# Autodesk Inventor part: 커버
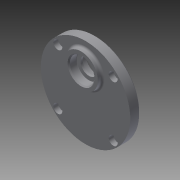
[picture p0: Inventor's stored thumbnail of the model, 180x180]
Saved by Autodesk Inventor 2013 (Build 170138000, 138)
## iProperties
Created: 2015-07
Part Number: 커버
Material: 일반
Document SubType Name: Modeling
Designer: user
Density: 1 g/cm^3
Author: user
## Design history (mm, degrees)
sketch "스케치1"
  geometry: C1 r 40 at (0, 0); 1 further point
  constraints: 1 centre point, 1 coincident
  dimensions: "d0" = 80 diameter of C1
extrude "돌출1" new body sketch "스케치1" distance "d1" = 9; taper "d2" = 0 deg
sketch "스케치2"
  geometry: L1 (0, 0)-(0, 11); L2 (0, 0)-(0, -20); C1 r 40 at (0, 0) reference; C2 r 14 at (0, 11); C3 r 14 at (0, -20)
  constraints: 4 end point, 2 centre point, 2 coincident, 1 collinear, 1 vertical
  dimensions: "d3" = 11 distance of L1.start L1.end; "d4" = 20 distance of L1.start L2.end; "d5" = 28 diameter of C2; "d6" = 28 diameter of C3
extrude "돌출2" join sketch "스케치2" distance "d7" = 3; taper "d8" = 0 deg
sketch "스케치3"
  geometry: C1 r 14 at (0, 0) reference; C2 r 14 at (0, -31) reference; C3 r 11 at (0, 0); C4 r 11 at (0, -29.914); 1 further point
  constraints: 2 centre point, 1 coincident
  dimensions: "d9" = 22 diameter of C3; "d10" = 22 diameter of C4
extrude "돌출3" cut sketch "스케치3" distance "d11" = 7; taper "d12" = 0 deg
sketch "스케치4"
  geometry: C1 r 9 at (0, 0); 2 further points
  constraints: 1 centre point, 1 coincident, 1 vertical alignment
  dimensions: "d13" = 18 diameter of C1
extrude "돌출4" cut sketch "스케치4" distance "d14" = 1; taper "d15" = 0 deg
sketch "스케치5"
  geometry: C1 r 11 at (0, 0) reference; C2 r 7.5 at (0, 0); 1 further point
  constraints: 1 centre point, 1 coincident
  dimensions: "d16" = 15 diameter of C2
extrude "돌출5" cut sketch "스케치5" distance "d17" = 2; taper "d18" = 0 deg
sketch "스케치6"
  geometry: C1 r 7.5 at (0, 0) reference; C2 r 11 at (0, 0); 1 further point
  constraints: 1 centre point, 1 coincident
  dimensions: "d19" = 22 diameter of C2
extrude "돌출6" cut sketch "스케치6" distance "d20" = 10; taper "d21" = 0 deg
sketch "스케치7"
  geometry: C1 r 11 at (0, 18.914) reference; C2 r 15 at (0, 18.914)
  constraints: 1 centre point, 1 coincident
  dimensions: "d22" = 30 diameter of C2
extrude "돌출7" join sketch "스케치7" distance "d23" = 4; taper "d24" = 0 deg
sketch "스케치8"
  geometry: L1 (0, 0)-(35, 0); L2 (0, 0)-(24.749, 24.749); C1 r 40 at (0, 0) reference; A1 r 35 centre (0, 0) between (35, 0) and (24.749, 24.749)
  constraints: 4 end point, 2 point on circle, 1 centre point, 1 coincident, 1 horizontal
  dimensions: "d25" = 70 diameter of A1; "d26" = 45 deg angle of L1 L2
hole "구멍1" sketch "스케치8" at (24.749, 24.749) diameter "d28" = 4.5; stored, may be unused: countersink angle "d32" = 90 deg, drill point angle "d34" = 118 deg; dims "d29" = 6, "d30" = 8, "d31" = 4.4, "d33" = 20
chamfer "모따기1" distance "d38" = 1; stored, may be unused: second distance "d39" = 2, angle "d40" = 45 deg
fillet "모깎기1" dims "d41" = 2
fillet "모깎기2" dims "d42" = 2
fillet "모깎기3" dims "d43" = 0.3
fillet "모깎기4" dims "d44" = 1
node "솔리드1"
pattern_circular "원형 패턴1" dims angle "d36" = 360 deg
node "투영된 루프1"
